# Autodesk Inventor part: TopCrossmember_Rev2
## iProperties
Created: 2008-11
Part Number: TopCrossmember_Rev2
Document SubType Name: Modeling
Designer: ETUDIANT
Author: ETUDIANT
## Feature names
1. Base1
